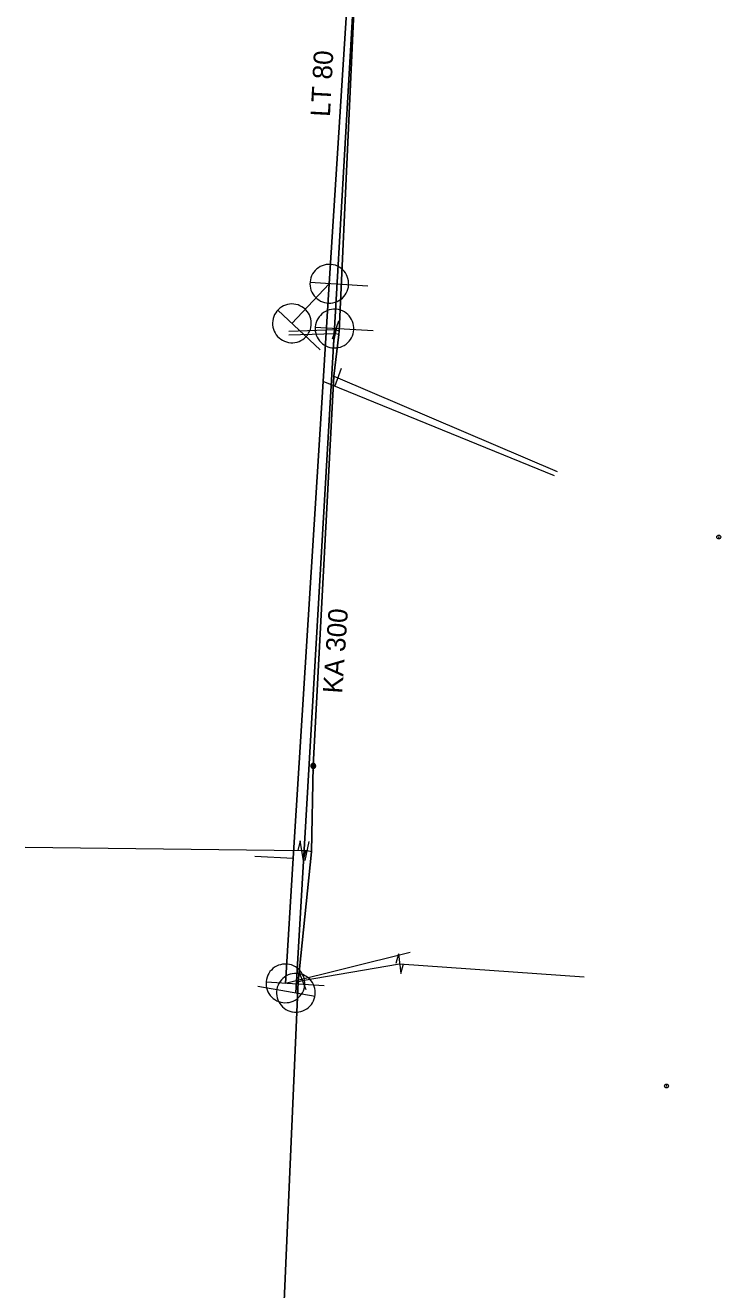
# Model space of a CAD drawing. Extents: x -783064 to -782702, y -1007904 to -1007145.
# Drawn here: x -783039.4 to -783003.6, y -1007512.4 to -1007447.2 of the extents above; entities that cross this region are included whole.
import ezdxf

# ---------------------------------------------------------------- set-up
doc = ezdxf.new("R2010")
doc.units = 0
doc.header["$LTSCALE"] = 0.4
doc.header["$PDMODE"] = 32
doc.header["$PDSIZE"] = 0.2
for name, color, linetype, lineweight in [('1', 7, 'Continuous', 13), ('11', 7, 'Continuous', 13), ('13', 7, 'Continuous', 13), ('14', 7, 'Continuous', 13), ('17', 7, 'Continuous', 25), ('22', 7, 'Continuous', 13), ('34', 7, 'Continuous', 13), ('47', 7, 'Continuous', 13), ('9', 7, 'Continuous', 13)]:
    doc.layers.add(name, color=color, linetype=linetype, lineweight=lineweight)

msp = doc.modelspace()

# ---------------------------------------------------------------- linework, layer by layer
at = {"layer": '1'}
for p in [(-783003.66, -1007473.599), (-783006.359, -1007501.929)]:
    msp.add_point(p, dxfattribs=at)
at = {"layer": '11'}
for p, q in [((-783025.686, -1007462.569), (-783023.759, -1007460.525)), ((-783012.145, -1007470.441), (-783024.074, -1007465.563)), ((-783027.596, -1007490.062), (-783025.618, -1007490.18)), ((-783019.588, -1007495.047), (-783026.022, -1007496.633))]:
    msp.add_line(p, q, dxfattribs=at)
at = {"layer": '13'}
for p, q in [((-783023.431, -1007462.903), (-783025.846, -1007462.992)), ((-783023.432, -1007463.11), (-783025.844, -1007463.181)), ((-783023.32, -1007465.375), (-783012, -1007470.221)), ((-783025.175, -1007489.786), (-783039.445, -1007489.618)), ((-783024.907, -1007489.796), (-783025.175, -1007489.786)), ((-783025.153, -1007496.481), (-783020.129, -1007495.618)), ((-783020.129, -1007495.618), (-783010.609, -1007496.3))]:
    msp.add_line(p, q, dxfattribs=at)
at = {"layer": '14', "lineweight": 25}
for p, q in [((-783023.759, -1007460.525), (-783020.12, -1007402.89)), ((-783025.48, -1007497.12), (-783023.489, -1007462.841))]:
    msp.add_line(p, q, dxfattribs=at)
at = {"layer": '14'}
for p, q in [((-783023.248, -1007462.969), (-783023.431, -1007462.903)), ((-783023.271, -1007463.144), (-783023.432, -1007463.11)), ((-783023.528, -1007465.299), (-783023.32, -1007465.375)), ((-783024.673, -1007489.846), (-783024.907, -1007489.796)), ((-783025.357, -1007496.559), (-783025.153, -1007496.481))]:
    msp.add_line(p, q, dxfattribs=at)
at = {"layer": '14', "lineweight": 25}
for points in [[(-783023.489, -1007462.841), (-783020.044, -1007403.091), (-783019.879, -1007391.6)], [(-783026.022, -1007496.633), (-783025.618, -1007490.18), (-783024.074, -1007465.563), (-783023.759, -1007460.525)]]:
    msp.add_lwpolyline(points, dxfattribs=at)
at = {"layer": '17'}
for points in [[(-783018.931, -1007392.572), (-783019.55, -1007405.538), (-783022.008, -1007435.982), (-783023.248, -1007462.969), (-783023.271, -1007463.144), (-783023.528, -1007465.299), (-783024.585, -1007485.409)], [(-783024.585, -1007485.409), (-783024.673, -1007489.846), (-783025.357, -1007496.559), (-783026.379, -1007519.715), (-783027.813, -1007543.224), (-783028.291, -1007552.975), (-783028.377, -1007555.317), (-783026.241, -1007555.437)]]:
    msp.add_lwpolyline(points, dxfattribs=at)
at = {"layer": '22'}
for p, q in [((-783021.762, -1007460.649), (-783024.756, -1007460.462)), ((-783024.23, -1007463.941), (-783026.413, -1007461.883)), ((-783021.491, -1007462.956), (-783024.486, -1007462.783)), ((-783027.45, -1007496.772), (-783024.495, -1007497.293)), ((-783024.025, -1007496.758), (-783027.019, -1007496.57))]:
    msp.add_line(p, q, dxfattribs=at)
for points in [[(-783023.696, -1007459.526), (-783023.805, -1007459.526), (-783023.914, -1007459.537), (-783024.021, -1007459.56), (-783024.125, -1007459.594), (-783024.225, -1007459.64), (-783024.318, -1007459.696), (-783024.406, -1007459.763), (-783024.485, -1007459.838), (-783024.556, -1007459.922), (-783024.617, -1007460.012), (-783024.668, -1007460.109), (-783024.707, -1007460.212), (-783024.736, -1007460.317), (-783024.753, -1007460.425), (-783024.758, -1007460.535), (-783024.75, -1007460.644), (-783024.732, -1007460.752), (-783024.702, -1007460.857), (-783024.659, -1007460.958), (-783024.607, -1007461.054), (-783024.543, -1007461.144), (-783024.471, -1007461.225), (-783024.39, -1007461.3), (-783024.301, -1007461.364), (-783024.207, -1007461.418), (-783024.106, -1007461.462), (-783024.001, -1007461.494), (-783023.894, -1007461.515), (-783023.784, -1007461.524), (-783023.675, -1007461.521), (-783023.567, -1007461.506), (-783023.461, -1007461.479), (-783023.358, -1007461.441), (-783023.26, -1007461.392), (-783023.168, -1007461.332), (-783023.084, -1007461.263), (-783023.007, -1007461.185), (-783022.939, -1007461.099), (-783022.881, -1007461.006), (-783022.834, -1007460.907), (-783022.798, -1007460.804), (-783022.773, -1007460.697), (-783022.76, -1007460.588), (-783022.759, -1007460.479), (-783022.77, -1007460.37), (-783022.793, -1007460.263), (-783022.827, -1007460.159), (-783022.873, -1007460.059), (-783022.929, -1007459.965), (-783022.995, -1007459.878), (-783023.07, -1007459.798), (-783023.154, -1007459.728), (-783023.244, -1007459.666), (-783023.341, -1007459.616), (-783023.443, -1007459.575), (-783023.55, -1007459.547), (-783023.658, -1007459.53)], [(-783024.999, -1007461.841), (-783025.083, -1007461.771), (-783025.174, -1007461.71), (-783025.271, -1007461.659), (-783025.372, -1007461.619), (-783025.478, -1007461.59), (-783025.586, -1007461.573), (-783025.696, -1007461.569), (-783025.805, -1007461.576), (-783025.913, -1007461.595), (-783026.018, -1007461.626), (-783026.119, -1007461.668), (-783026.215, -1007461.721), (-783026.305, -1007461.784), (-783026.387, -1007461.857), (-783026.461, -1007461.938), (-783026.525, -1007462.026), (-783026.58, -1007462.121), (-783026.623, -1007462.222), (-783026.655, -1007462.326), (-783026.676, -1007462.433), (-783026.685, -1007462.543), (-783026.682, -1007462.652), (-783026.666, -1007462.761), (-783026.64, -1007462.867), (-783026.601, -1007462.969), (-783026.552, -1007463.067), (-783026.492, -1007463.159), (-783026.423, -1007463.244), (-783026.344, -1007463.32), (-783026.258, -1007463.388), (-783026.166, -1007463.446), (-783026.067, -1007463.493), (-783025.964, -1007463.529), (-783025.857, -1007463.554), (-783025.748, -1007463.567), (-783025.639, -1007463.568), (-783025.529, -1007463.557), (-783025.423, -1007463.534), (-783025.319, -1007463.5), (-783025.219, -1007463.454), (-783025.125, -1007463.398), (-783025.038, -1007463.331), (-783024.958, -1007463.256), (-783024.888, -1007463.172), (-783024.827, -1007463.081), (-783024.776, -1007462.985), (-783024.736, -1007462.883), (-783024.707, -1007462.776), (-783024.69, -1007462.668), (-783024.685, -1007462.559), (-783024.692, -1007462.45), (-783024.711, -1007462.342), (-783024.741, -1007462.237), (-783024.784, -1007462.136), (-783024.836, -1007462.04), (-783024.9, -1007461.95), (-783024.972, -1007461.868)], [(-783023.43, -1007461.842), (-783023.54, -1007461.842), (-783023.648, -1007461.854), (-783023.756, -1007461.878), (-783023.859, -1007461.912), (-783023.959, -1007461.958), (-783024.052, -1007462.015), (-783024.139, -1007462.082), (-783024.218, -1007462.157), (-783024.289, -1007462.241), (-783024.349, -1007462.332), (-783024.4, -1007462.429), (-783024.439, -1007462.532), (-783024.467, -1007462.638), (-783024.483, -1007462.746), (-783024.488, -1007462.856), (-783024.48, -1007462.965), (-783024.461, -1007463.073), (-783024.43, -1007463.178), (-783024.387, -1007463.279), (-783024.334, -1007463.374), (-783024.27, -1007463.464), (-783024.198, -1007463.545), (-783024.116, -1007463.619), (-783024.027, -1007463.683), (-783023.932, -1007463.736), (-783023.832, -1007463.779), (-783023.726, -1007463.811), (-783023.619, -1007463.832), (-783023.51, -1007463.84), (-783023.4, -1007463.836), (-783023.292, -1007463.821), (-783023.186, -1007463.793), (-783023.084, -1007463.755), (-783022.986, -1007463.706), (-783022.894, -1007463.645), (-783022.81, -1007463.576), (-783022.734, -1007463.497), (-783022.666, -1007463.411), (-783022.609, -1007463.318), (-783022.562, -1007463.218), (-783022.526, -1007463.115), (-783022.502, -1007463.009), (-783022.49, -1007462.899), (-783022.489, -1007462.79), (-783022.501, -1007462.681), (-783022.524, -1007462.575), (-783022.559, -1007462.47), (-783022.605, -1007462.371), (-783022.662, -1007462.277), (-783022.728, -1007462.19), (-783022.804, -1007462.111), (-783022.888, -1007462.041), (-783022.979, -1007461.979), (-783023.076, -1007461.93), (-783023.178, -1007461.89), (-783023.284, -1007461.862), (-783023.393, -1007461.845)], [(-783025.958, -1007495.634), (-783026.068, -1007495.634), (-783026.176, -1007495.645), (-783026.284, -1007495.668), (-783026.387, -1007495.702), (-783026.487, -1007495.748), (-783026.581, -1007495.804), (-783026.669, -1007495.87), (-783026.747, -1007495.946), (-783026.819, -1007496.029), (-783026.88, -1007496.12), (-783026.931, -1007496.217), (-783026.97, -1007496.319), (-783026.999, -1007496.425), (-783027.016, -1007496.533), (-783027.021, -1007496.643), (-783027.013, -1007496.752), (-783026.995, -1007496.86), (-783026.965, -1007496.965), (-783026.922, -1007497.066), (-783026.87, -1007497.161), (-783026.806, -1007497.252), (-783026.734, -1007497.333), (-783026.653, -1007497.407), (-783026.565, -1007497.472), (-783026.47, -1007497.526), (-783026.369, -1007497.57), (-783026.264, -1007497.602), (-783026.157, -1007497.623), (-783026.048, -1007497.632), (-783025.938, -1007497.629), (-783025.83, -1007497.614), (-783025.724, -1007497.587), (-783025.622, -1007497.549), (-783025.523, -1007497.5), (-783025.431, -1007497.44), (-783025.347, -1007497.371), (-783025.27, -1007497.293), (-783025.202, -1007497.207), (-783025.144, -1007497.114), (-783025.097, -1007497.015), (-783025.061, -1007496.912), (-783025.036, -1007496.806), (-783025.023, -1007496.696), (-783025.022, -1007496.587), (-783025.033, -1007496.478), (-783025.056, -1007496.371), (-783025.09, -1007496.267), (-783025.136, -1007496.167), (-783025.192, -1007496.073), (-783025.258, -1007495.986), (-783025.333, -1007495.906), (-783025.417, -1007495.836), (-783025.507, -1007495.774), (-783025.604, -1007495.724), (-783025.706, -1007495.683), (-783025.812, -1007495.655), (-783025.921, -1007495.638)], [(-783025.654, -1007498.104), (-783025.545, -1007498.117), (-783025.436, -1007498.118), (-783025.326, -1007498.107), (-783025.22, -1007498.085), (-783025.115, -1007498.051), (-783025.016, -1007498.005), (-783024.922, -1007497.949), (-783024.835, -1007497.883), (-783024.755, -1007497.808), (-783024.684, -1007497.725), (-783024.622, -1007497.634), (-783024.572, -1007497.536), (-783024.531, -1007497.435), (-783024.503, -1007497.329), (-783024.485, -1007497.221), (-783024.48, -1007497.112), (-783024.487, -1007497.002), (-783024.505, -1007496.894), (-783024.536, -1007496.789), (-783024.577, -1007496.689), (-783024.63, -1007496.592), (-783024.693, -1007496.503), (-783024.766, -1007496.42), (-783024.846, -1007496.346), (-783024.934, -1007496.281), (-783025.029, -1007496.227), (-783025.13, -1007496.183), (-783025.234, -1007496.15), (-783025.342, -1007496.129), (-783025.451, -1007496.12), (-783025.56, -1007496.122), (-783025.668, -1007496.138), (-783025.775, -1007496.164), (-783025.878, -1007496.201), (-783025.976, -1007496.251), (-783026.067, -1007496.31), (-783026.153, -1007496.379), (-783026.229, -1007496.457), (-783026.297, -1007496.543), (-783026.355, -1007496.636), (-783026.403, -1007496.734), (-783026.44, -1007496.837), (-783026.465, -1007496.945), (-783026.478, -1007497.053), (-783026.479, -1007497.163), (-783026.468, -1007497.271), (-783026.446, -1007497.379), (-783026.411, -1007497.483), (-783026.366, -1007497.583), (-783026.31, -1007497.677), (-783026.245, -1007497.764), (-783026.169, -1007497.844), (-783026.086, -1007497.915), (-783025.996, -1007497.976), (-783025.899, -1007498.027), (-783025.796, -1007498.068), (-783025.691, -1007498.097)]]:
    msp.add_lwpolyline(points, close=True, dxfattribs=at)
at = {"layer": '34'}
for p, q in [((-783023.6, -1007463.373), (-783023.26, -1007462.432)), ((-783023.534, -1007463.599), (-783023.328, -1007462.62)), ((-783023.148, -1007464.905), (-783023.492, -1007465.844)), ((-783025.01, -1007490.285), (-783024.802, -1007489.307)), ((-783025.332, -1007496.014), (-783024.974, -1007496.948))]:
    msp.add_line(p, q, dxfattribs=at)
at = {"layer": '47'}
for p, q in [((-783025.095, -1007490.289), (-783024.974, -1007489.793)), ((-783020.191, -1007495.112), (-783020.329, -1007495.603))]:
    msp.add_line(p, q, dxfattribs=at)
for points in [[(-783025.095, -1007490.289), (-783025.254, -1007489.282), (-783025.375, -1007489.778)], [(-783020.191, -1007495.112), (-783020.066, -1007496.123), (-783019.928, -1007495.632)]]:
    msp.add_lwpolyline(points, dxfattribs=at)
at = {"layer": '9'}
msp.add_line((-783024.586, -1007485.536), (-783024.586, -1007485.661), dxfattribs=at)
for points in [[(-783024.712, -1007485.408), (-783024.711, -1007485.421), (-783024.709, -1007485.434), (-783024.706, -1007485.447), (-783024.701, -1007485.459), (-783024.695, -1007485.471), (-783024.688, -1007485.482), (-783024.68, -1007485.492), (-783024.67, -1007485.502), (-783024.66, -1007485.51), (-783024.649, -1007485.517), (-783024.637, -1007485.523), (-783024.625, -1007485.528), (-783024.612, -1007485.531), (-783024.599, -1007485.533), (-783024.586, -1007485.536), (-783024.573, -1007485.535), (-783024.56, -1007485.533), (-783024.547, -1007485.53), (-783024.535, -1007485.525), (-783024.523, -1007485.519), (-783024.512, -1007485.512), (-783024.502, -1007485.504), (-783024.492, -1007485.494), (-783024.484, -1007485.484), (-783024.477, -1007485.473), (-783024.471, -1007485.461), (-783024.466, -1007485.449), (-783024.463, -1007485.436), (-783024.461, -1007485.423), (-783024.459, -1007485.41), (-783024.46, -1007485.397), (-783024.462, -1007485.384), (-783024.465, -1007485.371), (-783024.47, -1007485.359), (-783024.476, -1007485.347), (-783024.483, -1007485.336), (-783024.491, -1007485.326), (-783024.501, -1007485.316), (-783024.511, -1007485.308), (-783024.522, -1007485.301), (-783024.534, -1007485.295), (-783024.546, -1007485.29), (-783024.559, -1007485.287), (-783024.572, -1007485.285), (-783024.585, -1007485.282), (-783024.598, -1007485.283), (-783024.611, -1007485.285), (-783024.624, -1007485.288), (-783024.636, -1007485.293), (-783024.648, -1007485.299), (-783024.659, -1007485.306), (-783024.669, -1007485.314), (-783024.679, -1007485.324), (-783024.687, -1007485.334), (-783024.694, -1007485.345), (-783024.7, -1007485.357), (-783024.705, -1007485.369), (-783024.708, -1007485.382), (-783024.71, -1007485.395)], [(-783024.692, -1007485.408), (-783024.692, -1007485.419), (-783024.69, -1007485.43), (-783024.687, -1007485.441), (-783024.683, -1007485.451), (-783024.678, -1007485.461), (-783024.672, -1007485.47), (-783024.665, -1007485.479), (-783024.657, -1007485.487), (-783024.648, -1007485.494), (-783024.639, -1007485.5), (-783024.629, -1007485.505), (-783024.619, -1007485.509), (-783024.608, -1007485.512), (-783024.597, -1007485.514), (-783024.586, -1007485.514), (-783024.575, -1007485.516), (-783024.564, -1007485.514), (-783024.553, -1007485.511), (-783024.543, -1007485.507), (-783024.533, -1007485.502), (-783024.524, -1007485.496), (-783024.515, -1007485.489), (-783024.507, -1007485.481), (-783024.5, -1007485.472), (-783024.494, -1007485.463), (-783024.489, -1007485.453), (-783024.485, -1007485.443), (-783024.482, -1007485.432), (-783024.48, -1007485.421), (-783024.479, -1007485.41), (-783024.479, -1007485.399), (-783024.481, -1007485.388), (-783024.484, -1007485.377), (-783024.488, -1007485.367), (-783024.493, -1007485.357), (-783024.499, -1007485.348), (-783024.506, -1007485.339), (-783024.514, -1007485.331), (-783024.523, -1007485.324), (-783024.532, -1007485.318), (-783024.542, -1007485.313), (-783024.552, -1007485.309), (-783024.563, -1007485.306), (-783024.574, -1007485.304), (-783024.585, -1007485.303), (-783024.596, -1007485.302), (-783024.607, -1007485.304), (-783024.618, -1007485.307), (-783024.628, -1007485.311), (-783024.638, -1007485.316), (-783024.647, -1007485.322), (-783024.656, -1007485.329), (-783024.664, -1007485.337), (-783024.671, -1007485.346), (-783024.677, -1007485.355), (-783024.682, -1007485.365), (-783024.686, -1007485.375), (-783024.689, -1007485.386), (-783024.691, -1007485.397)], [(-783024.673, -1007485.408), (-783024.672, -1007485.417), (-783024.671, -1007485.426), (-783024.668, -1007485.435), (-783024.665, -1007485.443), (-783024.661, -1007485.451), (-783024.656, -1007485.459), (-783024.65, -1007485.466), (-783024.644, -1007485.472), (-783024.637, -1007485.478), (-783024.629, -1007485.483), (-783024.621, -1007485.487), (-783024.613, -1007485.49), (-783024.604, -1007485.493), (-783024.595, -1007485.494), (-783024.586, -1007485.497), (-783024.577, -1007485.496), (-783024.568, -1007485.495), (-783024.559, -1007485.492), (-783024.551, -1007485.489), (-783024.543, -1007485.485), (-783024.535, -1007485.48), (-783024.528, -1007485.474), (-783024.522, -1007485.468), (-783024.516, -1007485.461), (-783024.511, -1007485.453), (-783024.507, -1007485.445), (-783024.504, -1007485.437), (-783024.501, -1007485.428), (-783024.5, -1007485.419), (-783024.498, -1007485.41), (-783024.499, -1007485.401), (-783024.5, -1007485.392), (-783024.503, -1007485.383), (-783024.506, -1007485.375), (-783024.51, -1007485.367), (-783024.515, -1007485.359), (-783024.521, -1007485.352), (-783024.527, -1007485.346), (-783024.534, -1007485.34), (-783024.542, -1007485.335), (-783024.55, -1007485.331), (-783024.558, -1007485.328), (-783024.567, -1007485.325), (-783024.576, -1007485.324), (-783024.585, -1007485.321), (-783024.594, -1007485.322), (-783024.603, -1007485.323), (-783024.612, -1007485.326), (-783024.62, -1007485.329), (-783024.628, -1007485.333), (-783024.636, -1007485.338), (-783024.643, -1007485.344), (-783024.649, -1007485.35), (-783024.655, -1007485.357), (-783024.66, -1007485.365), (-783024.664, -1007485.373), (-783024.667, -1007485.381), (-783024.67, -1007485.39), (-783024.671, -1007485.399)], [(-783024.653, -1007485.408), (-783024.653, -1007485.415), (-783024.651, -1007485.422), (-783024.65, -1007485.429), (-783024.647, -1007485.435), (-783024.644, -1007485.441), (-783024.64, -1007485.447), (-783024.636, -1007485.453), (-783024.631, -1007485.458), (-783024.625, -1007485.462), (-783024.619, -1007485.466), (-783024.613, -1007485.469), (-783024.607, -1007485.472), (-783024.6, -1007485.473), (-783024.593, -1007485.475), (-783024.586, -1007485.475), (-783024.579, -1007485.477), (-783024.572, -1007485.475), (-783024.565, -1007485.474), (-783024.559, -1007485.471), (-783024.552, -1007485.468), (-783024.547, -1007485.464), (-783024.541, -1007485.46), (-783024.536, -1007485.455), (-783024.532, -1007485.449), (-783024.528, -1007485.443), (-783024.525, -1007485.437), (-783024.522, -1007485.431), (-783024.52, -1007485.424), (-783024.519, -1007485.417), (-783024.518, -1007485.41), (-783024.518, -1007485.403), (-783024.519, -1007485.396), (-783024.521, -1007485.389), (-783024.524, -1007485.383), (-783024.527, -1007485.376), (-783024.531, -1007485.371), (-783024.535, -1007485.365), (-783024.54, -1007485.36), (-783024.546, -1007485.356), (-783024.551, -1007485.352), (-783024.558, -1007485.349), (-783024.564, -1007485.346), (-783024.571, -1007485.344), (-783024.578, -1007485.343), (-783024.585, -1007485.342), (-783024.592, -1007485.341), (-783024.599, -1007485.342), (-783024.606, -1007485.344), (-783024.612, -1007485.347), (-783024.618, -1007485.35), (-783024.624, -1007485.354), (-783024.63, -1007485.358), (-783024.635, -1007485.363), (-783024.639, -1007485.369), (-783024.643, -1007485.374), (-783024.646, -1007485.381), (-783024.649, -1007485.387), (-783024.65, -1007485.394), (-783024.652, -1007485.401)], [(-783024.633, -1007485.408), (-783024.633, -1007485.413), (-783024.632, -1007485.418), (-783024.631, -1007485.423), (-783024.629, -1007485.427), (-783024.627, -1007485.432), (-783024.624, -1007485.436), (-783024.621, -1007485.439), (-783024.617, -1007485.443), (-783024.614, -1007485.446), (-783024.61, -1007485.449), (-783024.605, -1007485.451), (-783024.601, -1007485.453), (-783024.596, -1007485.454), (-783024.591, -1007485.455), (-783024.586, -1007485.455), (-783024.581, -1007485.457), (-783024.576, -1007485.456), (-783024.571, -1007485.455), (-783024.567, -1007485.453), (-783024.562, -1007485.451), (-783024.558, -1007485.448), (-783024.554, -1007485.445), (-783024.551, -1007485.441), (-783024.548, -1007485.438), (-783024.545, -1007485.434), (-783024.543, -1007485.429), (-783024.541, -1007485.425), (-783024.54, -1007485.42), (-783024.539, -1007485.415), (-783024.539, -1007485.41), (-783024.538, -1007485.405), (-783024.539, -1007485.4), (-783024.54, -1007485.395), (-783024.542, -1007485.391), (-783024.544, -1007485.386), (-783024.547, -1007485.382), (-783024.55, -1007485.378), (-783024.553, -1007485.375), (-783024.557, -1007485.372), (-783024.561, -1007485.369), (-783024.566, -1007485.367), (-783024.57, -1007485.365), (-783024.575, -1007485.364), (-783024.58, -1007485.363), (-783024.585, -1007485.362), (-783024.59, -1007485.361), (-783024.595, -1007485.362), (-783024.6, -1007485.363), (-783024.604, -1007485.365), (-783024.609, -1007485.367), (-783024.613, -1007485.37), (-783024.616, -1007485.373), (-783024.62, -1007485.376), (-783024.623, -1007485.38), (-783024.626, -1007485.384), (-783024.628, -1007485.389), (-783024.63, -1007485.393), (-783024.631, -1007485.398), (-783024.632, -1007485.403)], [(-783024.613, -1007485.408), (-783024.613, -1007485.411), (-783024.613, -1007485.414), (-783024.612, -1007485.416), (-783024.611, -1007485.419), (-783024.61, -1007485.422), (-783024.608, -1007485.424), (-783024.606, -1007485.426), (-783024.604, -1007485.428), (-783024.602, -1007485.43), (-783024.6, -1007485.432), (-783024.597, -1007485.433), (-783024.594, -1007485.434), (-783024.592, -1007485.435), (-783024.589, -1007485.435), (-783024.586, -1007485.435), (-783024.583, -1007485.437), (-783024.58, -1007485.437), (-783024.577, -1007485.436), (-783024.575, -1007485.435), (-783024.572, -1007485.434), (-783024.57, -1007485.432), (-783024.567, -1007485.43), (-783024.565, -1007485.428), (-783024.564, -1007485.426), (-783024.562, -1007485.424), (-783024.561, -1007485.421), (-783024.56, -1007485.418), (-783024.559, -1007485.416), (-783024.559, -1007485.413), (-783024.557, -1007485.41), (-783024.558, -1007485.407), (-783024.558, -1007485.404), (-783024.559, -1007485.401), (-783024.56, -1007485.399), (-783024.561, -1007485.396), (-783024.563, -1007485.394), (-783024.564, -1007485.391), (-783024.566, -1007485.389), (-783024.569, -1007485.388), (-783024.571, -1007485.386), (-783024.574, -1007485.385), (-783024.576, -1007485.384), (-783024.579, -1007485.383), (-783024.582, -1007485.383), (-783024.585, -1007485.38), (-783024.588, -1007485.381), (-783024.591, -1007485.381), (-783024.593, -1007485.382), (-783024.596, -1007485.383), (-783024.599, -1007485.384), (-783024.601, -1007485.386), (-783024.603, -1007485.387), (-783024.605, -1007485.389), (-783024.607, -1007485.392), (-783024.609, -1007485.394), (-783024.61, -1007485.397), (-783024.611, -1007485.399), (-783024.612, -1007485.402), (-783024.612, -1007485.405)], [(-783024.594, -1007485.408), (-783024.594, -1007485.409), (-783024.594, -1007485.41), (-783024.593, -1007485.41), (-783024.593, -1007485.411), (-783024.593, -1007485.412), (-783024.592, -1007485.413), (-783024.592, -1007485.413), (-783024.591, -1007485.414), (-783024.591, -1007485.414), (-783024.59, -1007485.415), (-783024.589, -1007485.415), (-783024.588, -1007485.415), (-783024.588, -1007485.416), (-783024.587, -1007485.416), (-783024.586, -1007485.416), (-783024.585, -1007485.417), (-783024.584, -1007485.417), (-783024.584, -1007485.417), (-783024.583, -1007485.417), (-783024.582, -1007485.417), (-783024.581, -1007485.416), (-783024.581, -1007485.416), (-783024.58, -1007485.415), (-783024.58, -1007485.415), (-783024.579, -1007485.414), (-783024.579, -1007485.413), (-783024.578, -1007485.412), (-783024.578, -1007485.412), (-783024.578, -1007485.411), (-783024.577, -1007485.41), (-783024.577, -1007485.409), (-783024.577, -1007485.408), (-783024.577, -1007485.408), (-783024.578, -1007485.407), (-783024.578, -1007485.406), (-783024.579, -1007485.405), (-783024.579, -1007485.405), (-783024.58, -1007485.404), (-783024.58, -1007485.404), (-783024.581, -1007485.403), (-783024.582, -1007485.403), (-783024.583, -1007485.402), (-783024.583, -1007485.402), (-783024.584, -1007485.402), (-783024.585, -1007485.401), (-783024.586, -1007485.401), (-783024.587, -1007485.4), (-783024.587, -1007485.4), (-783024.588, -1007485.401), (-783024.589, -1007485.401), (-783024.59, -1007485.402), (-783024.59, -1007485.402), (-783024.591, -1007485.403), (-783024.591, -1007485.403), (-783024.592, -1007485.404), (-783024.592, -1007485.405), (-783024.592, -1007485.406), (-783024.593, -1007485.406), (-783024.593, -1007485.407)]]:
    msp.add_lwpolyline(points, close=True, dxfattribs=at)
msp.add_lwpolyline([(-783024.555, -1007485.627), (-783024.586, -1007485.661), (-783024.617, -1007485.625)], dxfattribs=at)

# ---------------------------------------------------------------- texts
at = {"layer": '1'}
for s, rotation, p in [('LT 80 ', 87, (-783023.726, -1007451.927)), ('KA 300', 86, (-783023.095, -1007481.696))]:
    msp.add_text(s, height=1, rotation=rotation, dxfattribs=at).set_placement(p)

doc.saveas('drawing.dxf')
